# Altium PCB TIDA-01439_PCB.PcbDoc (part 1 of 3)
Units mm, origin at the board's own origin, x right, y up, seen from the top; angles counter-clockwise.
Board outline 105.8 x 40.5 mm, 4 copper layers (Layer 1 - Top Layer, Layer 2 - GND, Layer 3 - POWER, Layer 4 - Bottom Layer), stack 1.56 mm thick; 145 components, 123 nets, 523 pads, 227 vias.
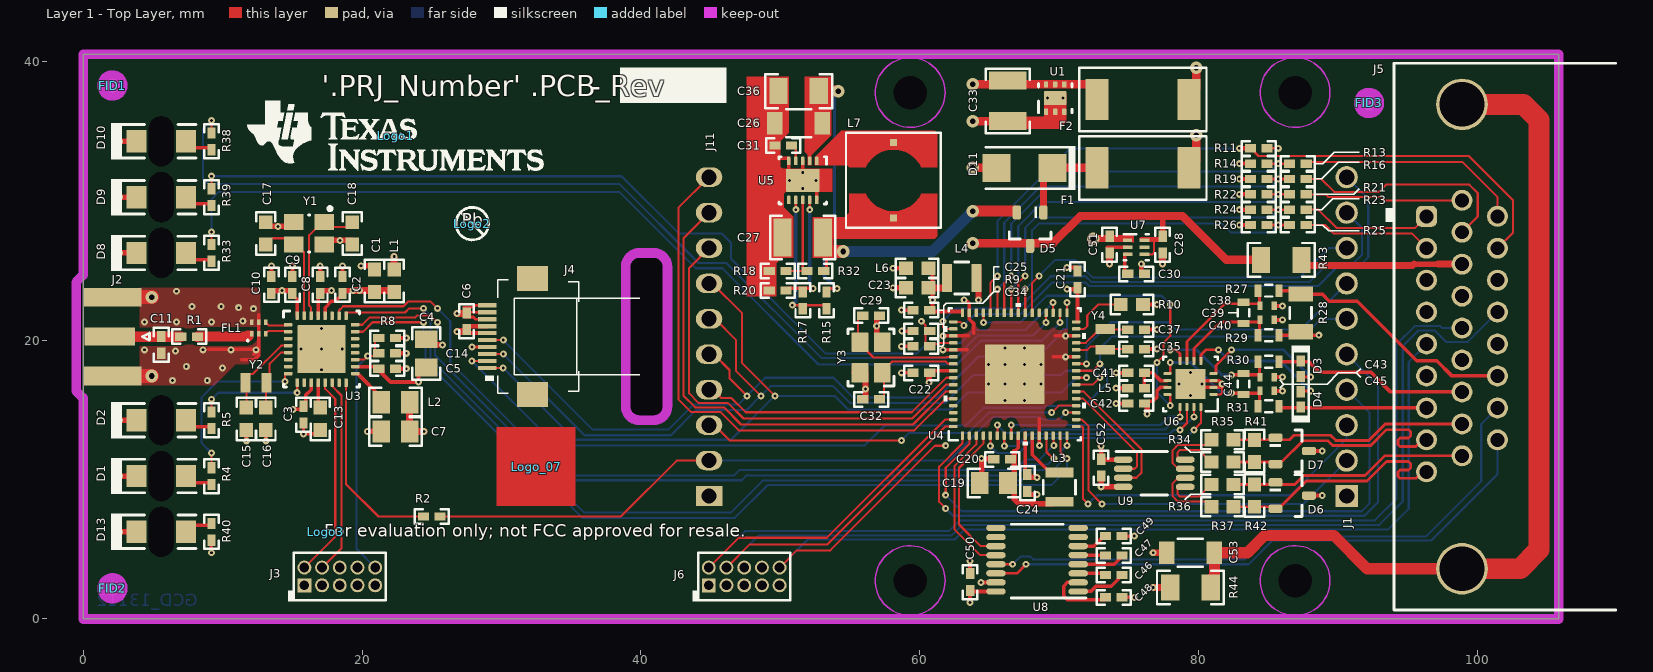
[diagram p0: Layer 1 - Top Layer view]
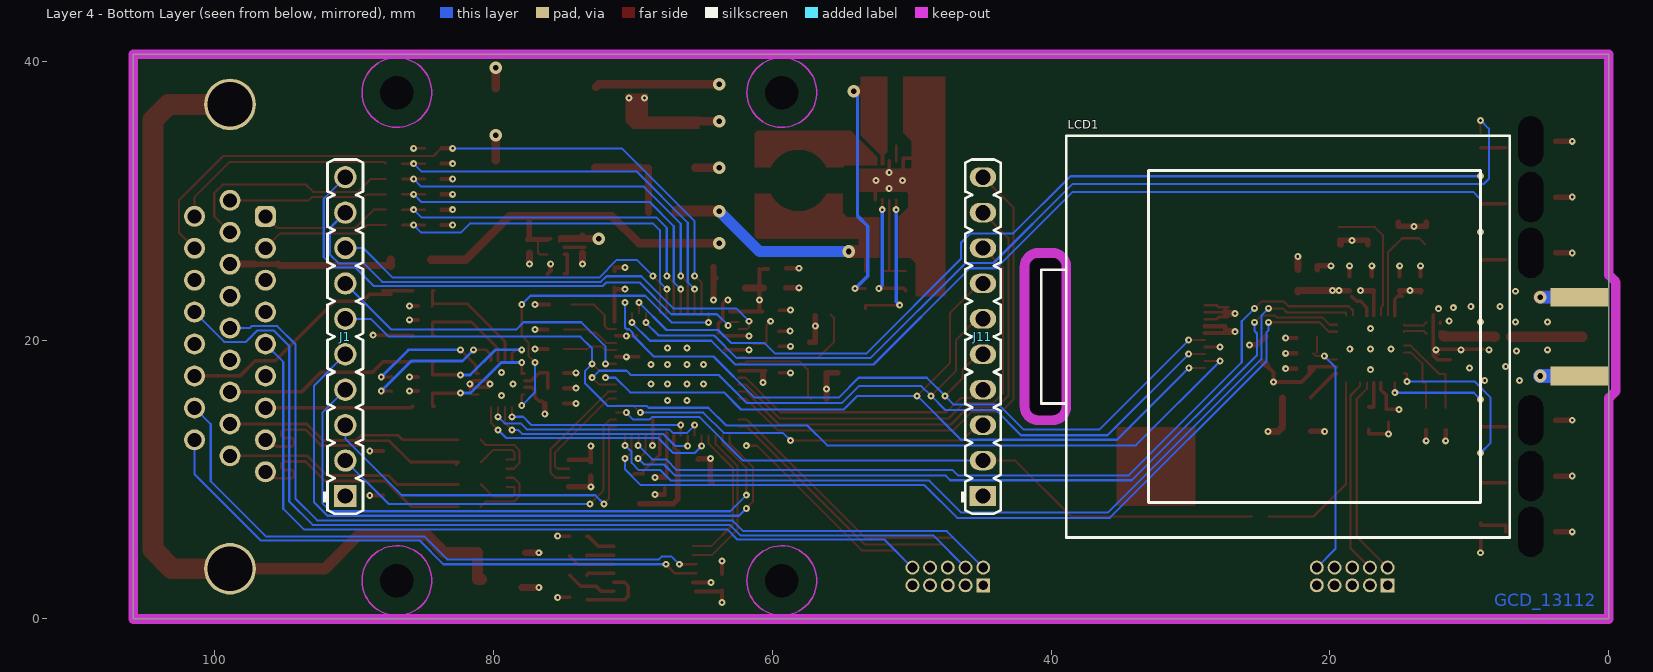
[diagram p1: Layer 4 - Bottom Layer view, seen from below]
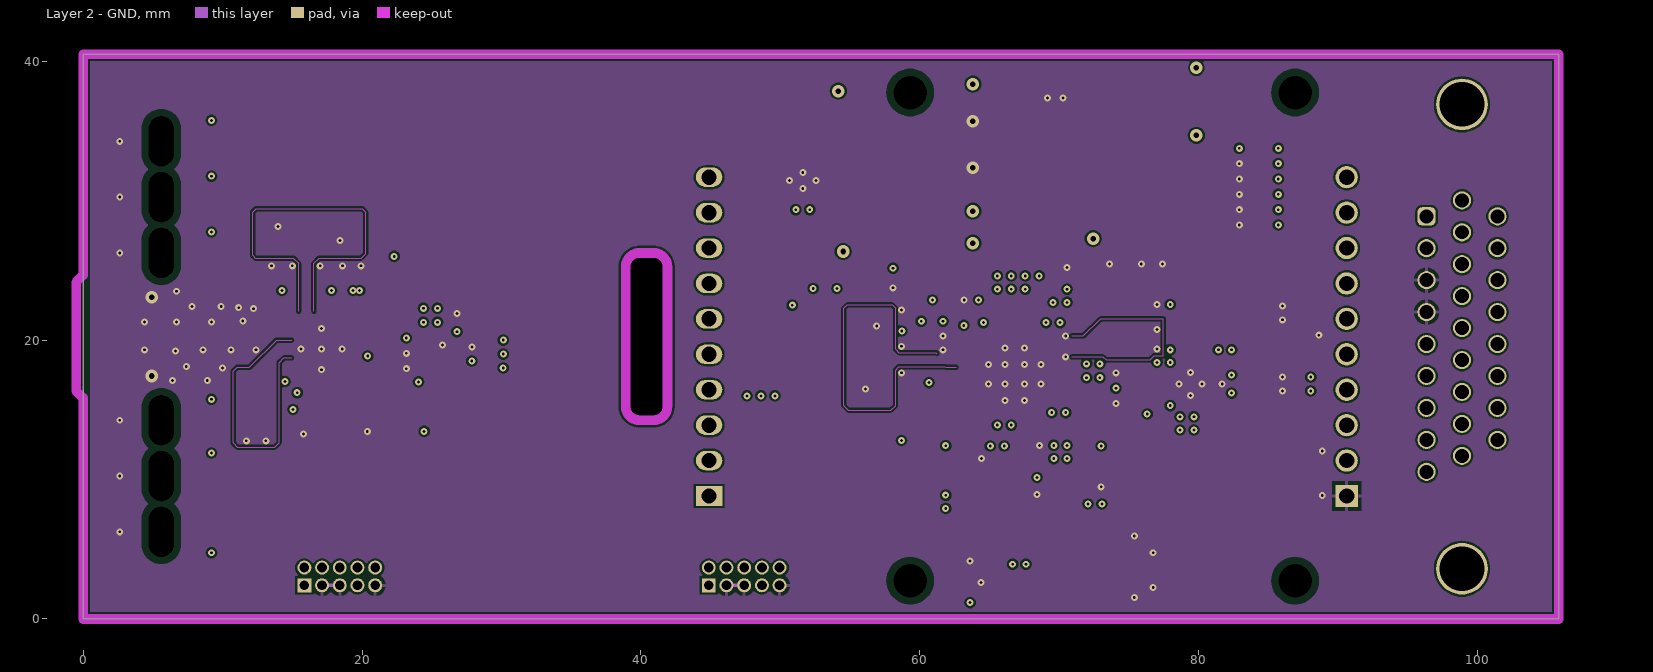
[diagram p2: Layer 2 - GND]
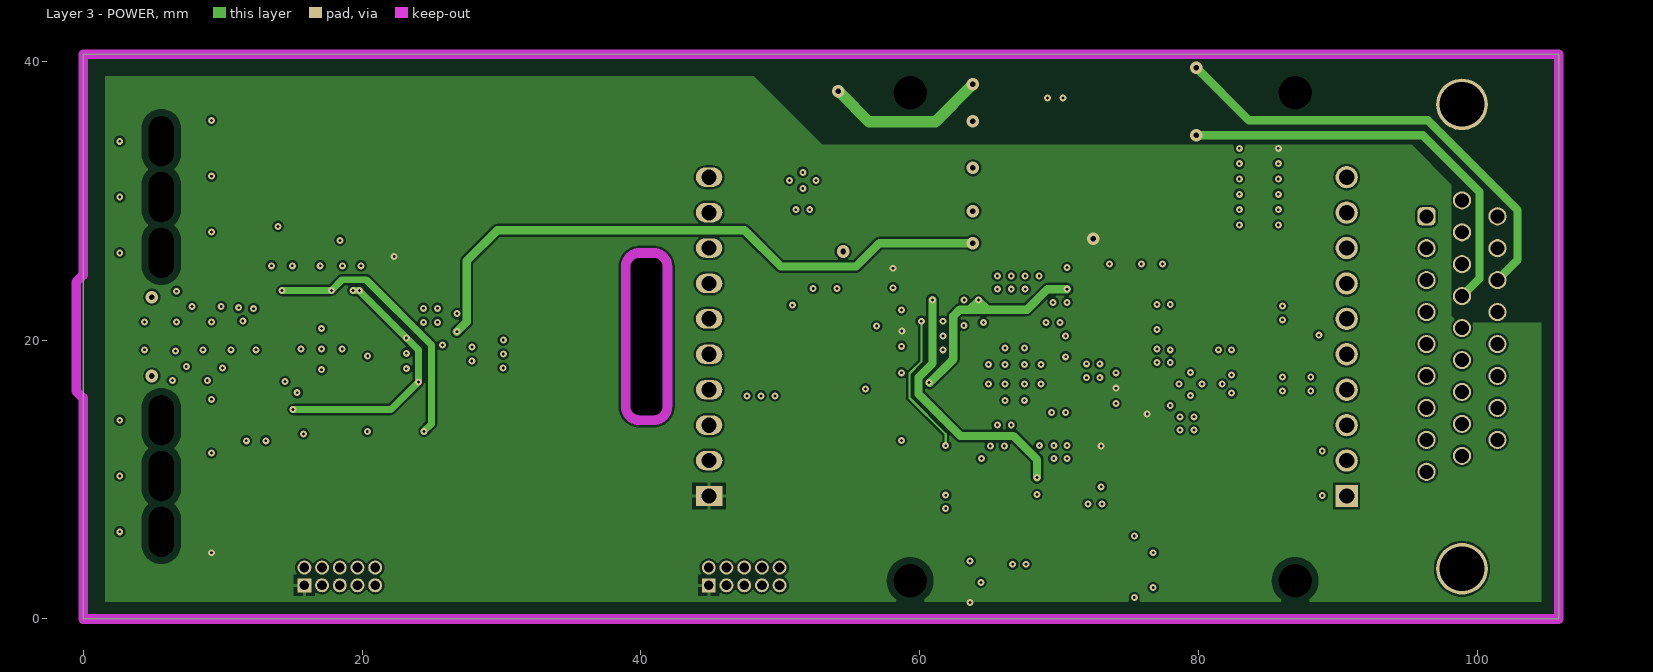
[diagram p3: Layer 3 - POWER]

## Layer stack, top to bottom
Top Solder: solder mask 0.0102, Solder Resist, Dk 3.5
Layer 1 - Top Layer: signal copper 0.0356
Dielectric1: prepreg 0.4724, 370HR, Dk 4.2
Layer 2 - GND: signal copper 0.0356
Dielectric3: core 0.4724, 370HR, Dk 4.2
Layer 3 - POWER: signal copper 0.0356
Dielectric2: prepreg 0.4724, 370HR, Dk 4.2
Layer 4 - Bottom Layer: signal copper 0.0356
Bottom Solder: solder mask 0.0102, Solder Resist, Dk 3.5

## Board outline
0,0 0,40.5 105.8,40.5 105.8,0
cut-out: 38.9,15.25 38.9,25.25 cw(c39.9,25.25) 39.9,26.25 40.9,26.25 cw(c40.9,25.25) 41.9,25.25 41.9,15.25 cw(c40.9,15.25) 40.9,14.25 39.9,14.25 cw(c39.9,15.25)

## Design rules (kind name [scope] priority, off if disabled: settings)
AssemblyTestPointUsage [All] p1: valid=2
BoardOutlineClearance [IsElectrical and not InComponent('J2')] p1: gap=0.5 ignorepadtopadclearanceinfootprint=FALSE
Clearance Clearance_PolyOnTop [(OnTop or OnBottom) and InPolygon] p1: gap=0.3 ignorepadtopadclearanceinfootprint=FALSE except(0: Arc-Hole Track-Hole SMDPad-Hole THPad-Hole Via-Hole Fill-Hole Poly-Hole Region-Hole Text-Hole)
Clearance Clearance_to-NPTHs [((ObjectKind = 'Pad') And (Layer = 'MultiLayer') And (PadIsPlated = 'False')) And (((AsMM(PadXSize_AllLayers) = 0.1) And (AsMM(PadYSize_AllLayers) = 0.1)) or (HoleType = 'Slot'))] p2: gap=0.5 ignorepadtopadclearanceinfootprint=FALSE except(0: Arc-Hole Track-Hole SMDPad-Hole THPad-Hole Via-Hole Fill-Hole Poly-Hole Region-Hole Text-Hole; 0.15: SMDPad-THPad)
Clearance Clearance_FiducialMark [IsKeepOut and InComponentClass('FiducialMark') vs IsPad and InComponentClass('FiducialMark')] p3: gap=0 ignorepadtopadclearanceinfootprint=FALSE
Clearance [All] p4: gap=0.15 ignorepadtopadclearanceinfootprint=FALSE except(0: Arc-Hole Track-Hole SMDPad-Hole THPad-Hole Via-Hole Fill-Hole Poly-Hole Region-Hole Text-Hole)
ComponentClearance ComponentClearance_Housing-to-J1 [(ObjectKind = '3D Body') And (Identifier = '82402224_BS_402_DIS-7024') vs InComponent('J1','J2','J5','J11')] p1: gap=0 collisioncheckmode=3 verticalgap=0 showdistances=FALSE
ComponentClearance [All  and not InComponent('FID3') vs All  and not InComponent('J5')] p2: gap=0.254 collisioncheckmode=3 verticalgap=0.254 showdistances=FALSE
DiffPairsRouting [All] p1: maxlimit=10 minlimit=0.125 mostfreqgap=0.15 toplayer_minwidth=0.381 toplayer_maxwidth=0.381 toplayer_prefwidth=0.381 midlayer1_minwidth=0.381 midlayer1_maxwidth=0.381 midlayer1_prefwidth=0.381 midlayer2_minwidth=0.381 midlayer2_maxwidth=0.381 midlayer2_prefwidth=0.381 bottomlayer_minwidth=0.381 bottomlayer_maxwidth=0.381 bottomlayer_prefwidth=0.381 maxuncoupledlength=12.7
FabricationTestPointUsage FabricationTestPointUsage_1 [All] p1: valid=2 allowmultiple=FALSE
FabricationTestpoint FabricationTestpoint_1 [All] p1: side=3 testpointundercomponent=TRUE minsize=1.016 maxsize=2.54 preferedsize=1.524 minholesize=0 maxholesize=1.016 preferedholesize=0.813 testpointgrid=0.025 allowsidetop=TRUE allowsidebottom=TRUE usegrid=TRUE gridtolerance=0
HoleSize [All] p1: absolutevalues=TRUE maxlimit=6 minlimit=0.2 maxpercent=80.000 minpercent=20.000
HoleSize FabricationTestpoint [All] p2 off: absolutevalues=TRUE maxlimit=2.54 minlimit=0.025 maxpercent=80.000 minpercent=20.000
HoleSize FabricationTestPointUsage [All] p3 off: absolutevalues=TRUE maxlimit=2.54 minlimit=0.025 maxpercent=80.000 minpercent=20.000
HoleToHoleClearance [All] p1: gap=0.2 allowstackedmicrovias=TRUE
MinimumAnnularRing [All] p1: minimumring=0.15
MinimumSolderMaskSliver [All] p1: minsoldermaskwidth=0.09
PlaneClearance [All] p1: clearance=0.5
PlaneConnect [All] p1: planeconnectstyle=Relief reliefexpansion=0.4 reliefentries=4 reliefconductorwidth=0.15 reliefairgap=0.15
PolygonConnect PolygonConnect_DirectConnect [(ObjectKind = 'Poly') And (Name = 'PolyDirectConnect')] p1: connectstyle=Direct reliefconductorwidth=0.254 reliefentries=4 polygonreliefangle="90 Angle" airgapwidth=0.254
PolygonConnect [IsVia] p2: connectstyle=Direct reliefconductorwidth=0.15 reliefentries=4 polygonreliefangle="90 Angle" airgapwidth=0.254
PolygonConnect "PolygonConnect_Thermal Relief" [All and not IsVia] p3: connectstyle=Relief reliefconductorwidth=0.25 reliefentries=4 polygonreliefangle="90 Angle" airgapwidth=0.25
PolygonConnect PolygonConnect_SMD [InPadClass('PolySMD')] p4: connectstyle=Relief reliefconductorwidth=0.254 reliefentries=4 polygonreliefangle="90 Angle" airgapwidth=0.254
RoutingCorners [All] p1: cornerstyle=45-Degree minsetback=1.25 maxsetback=1.25
RoutingVias [All] p1: holewidth=0.3 width=0.6 viastyle="Through Hole" minholewidth=0.2 minwidth=0.5 maxholewidth=0.6 maxwidth=1
SilkToBoardRegionClearance [Not ((IsComment or IsDesignator) And (Hide <> 'False')) and not InRegion(1000,500,4000,800)] p1:
SilkToSilkClearance [All and not InComponent('Logo2')] p1: silktosilkclearance=0.1
SilkToSolderMaskClearance [IsPad] p1: minsilkscreentomaskgap=0.1 clearancetoexposedcopper=TRUE
SolderMaskExpansion SolderMaskExpansion_Vias [IsVia] p1: expansion=0.025 soldermaskfromhole=TRUE
SolderMaskExpansion [All  and not IsVia] p2: expansion=0.05
Width [All] p1: maxlimit=10 minlimit=0.125 preferedwidth=0.15
16 further rules are at their usual default settings.

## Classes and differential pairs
component class TIDA-01439_CC2650: C1 C2 C3 C4 C5 C7 C8 C9 C10 C11 C13 C14 C15 C16 C17 C18 D1 D2 FL1 J2 J3 L1 L2 R1 R2 R4 R5 R8 U3 Y1 Y2
component class TIDA-01439_RTD: C38 C39 C40 C41 C42 C43 C44 C45 D3 D4 L5 R27 R28 R29 R30 R31 U6
component class TIDA-01439_Interface: C46 C47 C48 C49 C50 C52 C53 D6 D7 J5 R34 R35 R36 R37 R41 R42 R44 U8 U9
component class TIDA-01439_Powersupply: C26 C27 C28 C30 C31 C33 C36 C51 D5 D11 F1 F2 L7 R15 R17 R18 R20 R32 R43 U1 U5 U7
component class TIDA-01439_MSP432: C6 C19 C20 C21 C22 C23 C24 C25 C29 C32 C34 C35 C37 D8 D9 D10 D13 J1 J4 J6 J11 L3 L4 L6 R9 R10 R11 R13 R14 R16 R19 R21 R22 R23 R24 R25 R26 R33 R38 R39 R40 U4 Y3 Y4
component class Header: J1 J3 J6 J11
component class Logo: Logo1
component class TIDA-01439_EVM_Hardware: FID1 FID2 FID3 Logo1 Logo2 Logo3 ZZ1 ZZ2 ZZ3 ZZ4
component class FiducialMark: FID1 FID2 FID3
component class AssemblyNote: ZZ1 ZZ2 ZZ3 ZZ4

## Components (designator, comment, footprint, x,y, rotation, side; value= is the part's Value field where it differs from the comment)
C1 "Used in BOM report" 0603 20.9,24.25 r90 top
C2 "GRM155R70J104KA01D" 0402 18.6,23.95 r90 top value=0.1uF
C3 "GRM155R70J104KA01D" 0402 15.8,14.65 r270 top value=0.1uF
C4 "GRM21BR70J106KE76L" 0805_HV 24.6,19.05 r90 top value=10uF
C5 "GRM155R70J104KA01D" 0402 21.8,17.95 r0 top value=0.1uF
C6 "GRM155R70J104KA01D" 0402 27.5,21.35 r90 top value=0.1uF
C7 "GRM21BR70J106KE76L" 0805_HV 22.4,13.45 r180 top value=10uF
C8 "GRM155R70J104KA01D" 0402 17,23.95 r90 top value=0.1uF
C9 "GRM155R70J104KA01D" 0402 15,23.95 r90 top value=0.1uF
C10 "Used in BOM report" 0402 13.5,23.95 r90 top
C11 "Used in BOM report" 0402 5.6,19.65 r270 top
C13 "GRM188R70J105KA01D" 0603 17,14.35 r270 top value=1uF
C14 "GRM155R70J104KA01D" 0402 21.8,19.05 r0 top value=0.1uF
C15 "06035A220JAT2A" 0603 11.7,14.35 r90 top value=22pF
C16 "06035A220JAT2A" 0603 13.1,14.35 r270 top value=22pF
C17 "Used in BOM report" 0603 13.1,27.65 r90 top
C18 "Used in BOM report" 0603 19.3,27.65 r270 top
C19 "CC0805ZRY5V6BB475" 0805_HV 65.3,9.75 r180 top value=4.7uF
C20 "GRM155R70J104KA01D" 0402 65.9,11.45 r180 top value=0.1uF
C21 "GRM155R70J104KA01D" 0402 71.3,24.35 r90 top value=0.1uF
C22 "GRM155R70J104KA01D" 0402 60.1,17.65 r180 top value=0.1uF
C23 "GRM188R60J106ME47D" 0603 59.8,23.75 r180 top value=10uF
C24 "GRM155R70J104KA01D" 0402 67.7,9.75 r270 top value=0.1uF
C25 "GRM155R70J104KA01D" 0402 60.1,22.15 r180 top value=0.1uF
C26 "GRM31CR72A105KA01L" 1206_180 51.3,35.55 r180 top value=1uF
C27 "GRM32ER71A476KE15L" 1210_270 51.6,27.35 r180 top value=47uF
C28 "C1005X7S1A105K050BC" 0402 77.4,26.85 r270 top value=1uF
C29 "GRM1555C1H220JA01D" 0402 56.5,21.75 r180 top value=22pF
C30 "C1005X7R1C103K050BA" 0402 75.5,24.75 r0 top value=0.01uF
C31 "GRM155R71C473KA01D" 0402 50.2,33.95 r180 top value=0.047uF
C32 "GRM1555C1H220JA01D" 0402 56.5,15.75 r180 top value=22pF
C33 "GRM32ER71J106KA12L" 1210_270 66.3,37.15 r270 top value=10uF
C34 "GRM155R70J104KA01D" 0402 60.1,19.55 r180 top value=0.1uF
C35 "GRM1555C1H220JA01D" 0402 75.5,19.35 r180 top value=22pF
C36 "UMK316B7225KL-T" 1206 51.3,37.85 r180 top value=2.2uF
C37 "GRM1555C1H220JA01D" 0402 75.5,20.75 r180 top value=22pF
C38 "GRM155R72A182KA01D" 0402S 84.9,22.45 r0 top value=1800pF
C39 "C0603C183K1RACTU" 0603S 83.2,21.95 r270 top value=0.018uF
C40 "GRM155R72A182KA01D" 0402S 84.9,21.45 r180 top value=1800pF
C41 "GRM155R60J224KE01D" 0402 75.5,17.65 r180 top value=0.22uF
C42 "GRM155R60J224KE01D" 0402 75.5,15.45 r180 top value=0.22uF
C43 "GRM155R72A272KA01D" 0402S 84.9,17.35 r0 top value=2700pF
C44 "C0603C273K1RACTU" 0603S 83.2,16.85 r270 top value=0.027uF
C45 "GRM155R72A272KA01D" 0402S 84.9,16.35 r180 top value=2700pF
C46 "GRM155R70J104KA01D" 0402 73.9,3.15 r180 top value=0.1uF
C47 "GRM155R70J104KA01D" 0402 73.9,4.55 r180 top value=0.1uF
C48 "GRM155R70J104KA01D" 0402 73.9,1.55 r0 top value=0.1uF
C49 "GRM155R70J104KA01D" 0402 73.9,5.95 r0 top value=0.1uF
C50 "GRM155R70J104KA01D" 0402 63.6,2.65 r90 top value=0.1uF
C51 "C1005X7S1A105K050BC" 0402 73.6,26.85 r270 top value=1uF
C52 "GRM155R70J104KA01D" 0402 73,10.85 r270 top value=0.1uF
C53 "GRM31CR72E104KW03L" 1206_180 79.4,4.75 r0 top value=0.1uF
D1 "KPTL-3216CGCK-01" KPTL-3216-01_Green 5.6,10.25 r180 top value=Green
D2 "KPTL-3216SURCK-01" KPTL-3216-01_Red 5.6,14.25 r180 top value=Red
D3 "ZHCS350TA" SOD-523 87.3,17.95 r270 top value=40V
D4 "ZHCS350TA" SOD-523 87.3,15.75 r90 top value=40V
D5 "BAT54C-7-F" SOT-23 67.9,27.95 r270 top value=30V
D6 "CDSOT23-SM712" SOT-23 86.7,8.85 r0 top value=7V
D7 "CDSOT23-SM712" SOT-23 86.7,12.05 r0 top value=7V
D8 "KPTL-3216CGCK-01" KPTL-3216-01_Green 5.6,26.25 r180 top value=Green
D9 "KPTL-3216SURCK-01" KPTL-3216-01_Red 5.6,30.25 r180 top value=Red
D10 "KPTL-3216CGCK-01" KPTL-3216-01_Green 5.6,34.25 r180 top value=Green
D11 "SMAJ5.0A-TR" SMA 67.5,32.35 r180 top value=5V
D13 "KPTL-3216CGCK-01" KPTL-3216-01_Green 5.6,6.25 r180 top value=Green
F1 "0459.500" PicoSMF459 76,32.35 r0 top
F2 "0459.500" PicoSMF459 76,37.25 r0 top
FID1 "Fiducial" Fiducial10-20 2.1,38.25 r0 top
FID2 "Fiducial" Fiducial10-20 2.1,2.2 r0 top
FID3 "Fiducial" Fiducial10-20 92.2,37 r0 top
FL1 "LFB182G45BG5D920" Murata_LFB182G45BG5D920 12.579,20.865 r90 top value="2.45 GHz"
J1 "61301011121" Wurth_61301011121#1 90.6,20.25 r90 bottom locked
J2 "SMA-J-P-H-ST-EM1" Samtec_SMA-J-P-H-ST-EM1 0,20.25 r270 top locked
J3 "GRPB052VWVN-RC" CONN_GRPB052VWVN-RC 18.4,3.05 r0 top
J4 "FH12-10S-0.5SH[55]" Hirose_FH12-10S-0_5SH[55] 30.6,20.25 r90 top locked
J5 "618026330923" Wurth_618026330923 110.3,20.25 r0 top locked
J6 "GRPB052VWVN-RC" CONN_GRPB052VWVN-RC 47.4,3.05 r0 top
J11 "61301011121" Wurth_61301011121#2 44.88,20.25 r90 bottom locked
L1 "BLM18HE152SN1D" 0603 22.3,24.25 r90 top value="1500 ohm"
L2 "CKS2125100M-T" 0805_HV 22.4,15.55 r0 top value=10uH
L3 "MLP2520S4R7ST0S1" MLP2520S-S 70,9.45 r270 top value=4.7uH
L4 "MLP2520S4R7ST0S1" MLP2520S-S 63,24.45 r0 top value=4.7uH
L5 "BLM15HG102SN1D" 0402 75.5,16.55 r0 top value="1000 ohm"
L6 "BLM18HE152SN1D" 0603 59.8,25.15 r180 top value="1500 ohm"
L7 "744053101" WE-TPC-LH 58.1,31.45 r270 top value=100uH
LCD1 "" LCD_LS013B7DH06 21.1,20.25 r270 bottom locked
Logo1 "Texas Instruments" TI_Stacked_Overlay_Small 22.4,34.65 r0 top
Logo2 "Pb-Free Symbol" Pb-Free_Overlay_Small 27.9,28.35 r0 top
Logo3 "FCC disclaimer" FCC_disclaimer 17.4,6.25 r0 top
Logo_07 "" GCD-Logo_5.5x5.5_SolderMask 32.475,10.925 r0 top
R1 "CRCW04020000Z0ED" 0402 7.6,20.25 r0 top value=0
R2 "CRCW04020000Z0ED" 0402 25,7.35 r0 top value=0
R4 "CRCW0402470RJNED" 0402 9.2,10.25 r90 top value=470
R5 "CRCW0402470RJNED" 0402 9.2,14.25 r270 top value=470
R8 "CRCW040247K5FKED" 0402 21.8,20.15 r0 top value=47.5k
R9 "CRCW0402100KJNED" 0402 60.1,20.65 r180 top value=100k
R10 "RG1608P-913-B-T5" 0603 75.2,22.55 r180 top value=91.0k
R11 "CRCW040210K0FKED" 0402 84.3,33.75 r0 top value=10.0k
R13 "CRCW040218K0FKED" 0402 87.1,32.65 r0 top value=18.0k
R14 "CRCW040233K0JNED" 0402 84.3,32.65 r0 top value=33k
R15 "CRCW04022M00FKED" 0402 53.3,22.85 r90 top value=2.00Meg
R16 "CRCW040218K0FKED" 0402 87.1,31.55 r0 top value=18.0k
R17 "CRCW0402130KJNED" 0402 51.6,22.85 r270 top value=130k
R18 "CRCW0402110KFKED" 0402 49.8,24.95 r0 top value=110k
R19 "CRCW040233K0JNED" 0402 84.3,31.55 r0 top value=33k
R20 "CRCW040224K9FKED" 0402 49.8,23.55 r0 top value=24.9k
R21 "CRCW040218K0FKED" 0402 87.1,30.45 r0 top value=18.0k
R22 "CRCW040233K0JNED" 0402 84.3,30.45 r0 top value=33k
R23 "CRCW040218K0FKED" 0402 87.1,29.35 r0 top value=18.0k
R24 "CRCW040233K0JNED" 0402 84.3,29.35 r0 top value=33k
R25 "CRCW040218K0FKED" 0402 87.1,28.25 r0 top value=18.0k
R26 "CRCW040233K0JNED" 0402 84.3,28.25 r0 top value=33k
R27 "RG1608P-4121-B-T5" 0603S 85,23.55 r180 top value=4.12k
R28 "PFC-W1206R-12-3241-B" 1206L 87.3,21.95 r90 top value=3.24k
R29 "RG1608P-4121-B-T5" 0603S 85,20.35 r180 top value=4.12k
R30 "RG1608P-4121-B-T5" 0603S 85,18.45 r180 top value=4.12k
R31 "RG1608P-4121-B-T5" 0603S 85,15.25 r180 top value=4.12k
R32 "CRCW0402383KFKED" 0402 52.5,24.95 r0 top value=383k
R33 "CRCW0402470RJNED" 0402 9.2,26.25 r90 top value=470
R34 "CRCW060310R0JNEAHP" 0603 81.7,11.25 r0 top value=10
R35 "CRCW060310R0JNEAHP" 0603 81.7,12.85 r0 top value=10
R36 "CRCW060310R0JNEAHP" 0603 81.7,9.65 r0 top value=10
R37 "CRCW060310R0JNEAHP" 0603 81.7,8.05 r0 top value=10
R38 "CRCW0402470RJNED" 0402 9.2,34.25 r270 top value=470
R39 "CRCW0402470RJNED" 0402 9.2,30.25 r270 top value=470
R40 "CRCW0402470RJNED" 0402 9.2,6.25 r90 top value=470
R41 "CRCW0603120RJNEA" 0603 84,12.05 r90 top value=120
R42 "CRCW0603120RJNEA" 0603 84,8.85 r270 top value=120
R43 "CRCW1206100RJNEA" 1206 85.9,25.75 r0 top value=100
R44 "CRCW1206100RJNEA" 1206 79.4,2.25 r0 top value=100
U1 "TVS3300DRVR" DRV0006A 69.7,37.35 r90 top
U3 "CC2650F128RHBR" RHB0032E 17.1,19.35 r0 top
U4 "MSP432P401RIRGCR" RGC0064B 66.8,17.55 r90 top
U5 "LM5165DRCR" DRC0010J 51.6,31.45 r270 top
U6 "ADS1220IRVAR" RVA0016A 79.4,16.85 r180 top
U7 "TPS71733DSER" DSE0006A 75.5,26.65 r0 top
U8 "MAX3232EIPWR" PW0016A_N 68.4,4.25 r180 top
U9 "SN65HVD71DGKR" DGK0008A_N 76.8,10.45 r0 top
Y1 "TSX-3225 24.0000MF20G-AC3" EPSON_TSX-3225 16.2,27.65 r270 top
Y2 "FC-12M 32.7680KA-A3" Epson_FC-12M 12.4,16.95 r0 top
Y3 "FA-238 48.0000MB-W0" Epson_FA-238 56.5,18.75 r180 top
Y4 "FC-12M 32.7680KA-A3" Epson_FC-12M 73.3,20.05 r270 top
ZZ1 "This Assembly Note is for PCB labels only" AssemblyNoteLabel 4.399,82.075 r0 top
ZZ2 "These assemblies are ESD sensitive, ESD precautions shall be observed." AssemblyNote 4.399,79.309 r0 top
ZZ3 "These assemblies must be clean and free from flux and all contaminants. Use of no clean flux is not acceptable." AssemblyNote 4.399,77.06 r0 top
ZZ4 "These assemblies must comply with workmanship standards IPC-A-610 Class 2, unless otherwise specified." AssemblyNote 4.399,74.811 r0 top

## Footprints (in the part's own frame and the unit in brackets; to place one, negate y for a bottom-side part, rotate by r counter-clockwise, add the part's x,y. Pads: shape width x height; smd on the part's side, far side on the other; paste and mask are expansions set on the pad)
0402 [mm] "0402 from SM-752 data"
  rect 0.8x0.6 smd: 1(-0.6,0) 2(0.6,0)
  silkscreen extent -1.22,-0.52 1.22,0.52, body extent -0.55,-0.3 0.55,0.3, height 0.6
0402S [mil] "Based on C0402S footprint from PADS legacy"
  rect 15x24 smd: 1(-20,0) 2(20,0)
  body extent -22,-12 22,12, height 24
0603 [mm] "0603 from SM-752 data"
  rect 1x0.95 smd: 1(-0.8,0) 2(0.8,0)
  silkscreen extent -1.52,-0.69 1.52,0.69, body extent -0.87,-0.47 0.87,0.47, height 1
0603S [mil]
  rect 20x35 smd: 1(-30,0) 2(30,0)
  silkscreen extent -10,-17 10,17, body extent -34,-19 34,19, height 39
0805_HV [mil] "0805 with 30mil clearance between pads"
  rect 50x63 smd: 1(-40,0) 2(40,0)
  silkscreen extent -74,-40 74,40, body extent -43,-29 43,29, height 57
1206 [mm] "1206 from SM-752 data"
  rect 1.3x1.85 smd: 1(-1.45,0) 2(1.45,0)
  silkscreen extent -2.4,-1.21 2.4,1.21, body extent -1.7,-0.9 1.7,0.9, height 1.35
1206_180 [mm] "1206_180"
  rect 1.1x1.6 smd: 1(-1.7,0) 2(1.7,0)
  silkscreen extent -0.9,-1 0.9,1, body extent -1.75,-0.95 1.75,0.95, height 1.8
1206L [mm] "1206 from SM-752 data"
  rect 1.1x1.75 smd: 1(-1.35,0) 2(1.35,0)
  silkscreen extent -0.4,-0.77 0.4,0.77, body extent -1.7,-0.9 1.7,0.9, height 1.35
1210_270 [mm] "1210"
  rect 1.3x2.7 smd: 1(-1.45,0) 2(1.45,0)
  silkscreen extent -2.32,-1.57 2.32,1.57, body extent -1.7,-1.35 1.7,1.35, height 2.7
AssemblyNote [mm] "Assembly Note"
AssemblyNoteLabel [mm] "Assembly Note for PCB Labels"
CONN_GRPB052VWVN-RC [mm] "SULLINS"
  rect 1x1 hole 0.7 mask+0.08: 1(-2.54,-0.635)
  round 1 hole 0.7 mask+0.08: 2(-2.54,0.635) 3(-1.27,-0.635) 4(-1.27,0.635) 5(0,-0.635) 6(0,0.635) 7(1.27,-0.635) 8(1.27,0.635) 9(2.54,-0.635) 10(2.54,0.635)
  silkscreen extent -3.7,-1.8 3.3,1.7, body extent -3.17,-1.7 3.17,1.7, height 4
DGK0008A_N [mm] "TSOP, 8-Leads, Body 3x3mm, Pitch 0.65mm, IPC Medium Density"
  oval 1.35x0.45 smd: 1(-2.225,0.975) 2(-2.225,0.325) 3(-2.225,-0.325) 4(-2.225,-0.975) 5(2.225,-0.975) 6(2.225,-0.325) 7(2.225,0.325) 8(2.225,0.975)
  silkscreen extent -2.75,-1.55 0.95,1.55, body extent -2.45,-1.5 2.45,1.5, height 0.96
DRC0010J [mm] "SON, 10-Leads, Body 3x3mm, Pitch 0.5mm, Thermal Pad 2.4x1.65mm, TI Recommended"
  rrect42% 0.6x0.24 smd: 1(-1.4,1) 2(-1.4,0.5) 3(-1.4,0) 4(-1.4,-0.5) 5(-1.4,-1) 6(1.4,-1) 7(1.4,-0.5) 8(1.4,0) 9(1.4,0.5) 10(1.4,1)
  rrect6% 1.65x2.4 smd paste-0.825: 11(0,0)
  silkscreen extent -1.7,-1.7 1.7,1.7, body extent -1.5,-1.5 1.5,1.5, height 0.77
DRV0006A [mm] "SON, 6-Leads, Body 2x2mm, Pitch 0.65mm, Thermal Pad 1.6x1mm, TI Recommended"
  rrect33% 0.45x0.3 smd: 1(-0.975,0.65) 2(-0.975,0) 3(-0.975,-0.65) 4(0.975,-0.65) 5(0.975,0) 6(0.975,0.65)
  rrect14% 1x0.7 on Top Paste: 7(0,0.45) 7(0,-0.45)
  rrect10% 1x1.6 smd paste-0.5: 7(0,0)
  silkscreen extent -1.05,-1.2 1.05,1.2, body extent -1.05,-1.05 1.05,1.05, height 0.81
DSE0006A [mm] "TI recommended land pattern"
  rect 0.66x0.25 smd: 1(-0.62,0.5)
  rect 0.7x0.25 smd: 2(-0.6,0) 3(-0.6,-0.5) 4(0.6,-0.5) 5(0.6,0) 6(0.6,0.5)
  Layer 1 - Top Layer region: -0.3,0.625 -0.25,0.625 -0.15,0.525 -0.15,0.375 -0.3,0.375
  silkscreen extent -0.9,-0.92 0.9,0.92, body extent -0.77,-0.77 0.77,0.77, height 0.8
Epson_FA-238 [mm] "SMD, 4-Leads, Body 3.2x2.5mm"
  rrect8% 1.2x1.4 smd: 1(-0.8,1.1) 2(-0.8,-1.1) 3(0.8,-1.1) 4(0.8,1.1)
  silkscreen extent -1.65,-2.05 1.65,2.05, body extent -1.3,-1.65 1.3,1.65, height 0.7
Epson_FC-12M [mm] "Epson"
  rect 0.7x1.4 smd: 1(-0.75,0) 2(0.75,0)
  body extent -1.05,-0.63 1.05,0.63, height 0.6
EPSON_TSX-3225 [mm] "SMD, 4-Leads, Body 2.65x3.35mm, Height 0.6mm"
  rect 1.15x1.4 smd: 1(-0.8,1.1) 2(-0.8,-1.1) 3(0.8,-1.1) 4(0.8,1.1)
  silkscreen extent -1.9,-0.05 1.33,1.63, body extent -1.33,-1.68 1.33,1.68, height 0.61
FCC_disclaimer [mm]
Fiducial10-20 [mm]
  round 1 smd mask+0.5: 1(0,0)
  Layer 1 - Top Layer keep-out circle w1.178: c0,0 r0.5
GCD-Logo_5.5x5.5_SolderMask [mm] "GCD-Logo, 5.55x5.55mm, SolderMask, 80µm, positive"
Hirose_FH12-10S-0_5SH[55] [mm] "Hirose, footprint recommended"
  rect 0.3x1.3 smd: 1(-2.254,1.626) 2(-1.754,1.626) 3(-1.254,1.626) 4(-0.754,1.626) 5(-0.253,1.626) 6(0.246,1.626) 7(0.746,1.626) 8(1.246,1.626) 9(1.746,1.626) 10(2.247,1.626)
  rect 1.8x2.2 smd: M1(-4.153,-1.622) M2(4.153,-1.626)
  silkscreen extent -4.06,-4.95 4.07,1.78, body extent -4.55,-4.88 4.56,0.84, height 2
KPTL-3216-01_Green [mm] "SMD, 2-Leads, Body 3.2x1.6mm"
  round 0 hole 1.8 slot 3.6 at 90 deg unplated: 0(0,0)
  rect 1.45x1.6 smd: 1(-1.78,0) 2(1.78,0)
  silkscreen extent -2.5,-1.3 3.6,1.3, body extent -1.65,-0.85 1.65,0.85, height 0.27
KPTL-3216-01_Red [mm] "SMD, 2-Leads, Body 3.2x1.6mm"
  round 0 hole 1.8 slot 3.6 at 90 deg unplated: 0(0,0)
  rect 1.45x1.6 smd: 1(-1.78,0) 2(1.78,0)
  silkscreen extent -2.5,-1.3 3.6,1.3, body extent -1.65,-0.85 1.65,0.85, height 0.27
LCD_LS013B7DH06 [mm] "Outline Display"
  silkscreen extent -14.4,-19.6 14.4,14, body extent -14.4,-17.8 14.4,14, height 0.85
MLP2520S-S [mm] "TDK"
  rect 0.7x2 smd: 1(-1.05,0) 2(1.05,0)
  silkscreen extent -0.5,-1.15 0.5,1.15, body extent -1.32,-1.07 1.32,1.07, height 1.2
Murata_LFB182G45BG5D920 [mm] "SMT, 6-Leads, Body 1.6x0.8mm, Pitch 0.5mm"
  rect 0.425x0.25 smd mask+0.07: 1(-0.413,0.5) 2(-0.413,0) 3(-0.413,-0.5) 4(0.412,-0.5) 5(0.412,0) 6(0.412,0.5)
  silkscreen extent -0.91,0.76 -0.89,0.78, body extent -0.45,-0.85 0.45,0.85, height 0.65
Pb-Free_Overlay_Small [mm]
  silkscreen extent -1.16,-1.17 1.17,1.17
PicoSMF459 [mm] "Littelfuse 459 Fuses, recommended land pattern"
  rect 1.65x2.97 smd: 1(-3.3,0) 2(3.3,0)
  silkscreen extent -4.57,-2.27 4.55,2.27, body extent -3.62,-2.17 3.61,2.14, height 3.05
PW0016A_N [mm] "TSOP, 16-Leads, Body 5x4.4mm, Pitch 0.65mm, IPC Medium Density"
  oval 1.4x0.45 smd: 1(-2.95,2.275) 2(-2.95,1.625) 3(-2.95,0.975) 4(-2.95,0.325) 5(-2.95,-0.325) 6(-2.95,-0.975) 7(-2.95,-1.625) 8(-2.95,-2.275) 9(2.95,-2.275) 10(2.95,-1.625) 11(2.95,-0.975) 12(2.95,-0.325) 13(2.95,0.325) 14(2.95,0.975) 15(2.95,1.625) 16(2.95,2.275)
  silkscreen extent -3.5,-2.55 1.85,2.75, body extent -3.21,-2.5 3.21,2.5, height 1
RGC0064B [mm]
  rrect42% 0.6x0.24 smd mask+0.07: 1(-4.4,3.75) 2(-4.4,3.25) 3(-4.4,2.75) 4(-4.4,2.25) 5(-4.4,1.75) 6(-4.4,1.25) 7(-4.4,0.75) 8(-4.4,0.25) 9(-4.4,-0.25) 10(-4.4,-0.75) 11(-4.4,-1.25) 12(-4.4,-1.75) 13(-4.4,-2.25) 14(-4.4,-2.75) 15(-4.4,-3.25) 16(-4.4,-3.75) 33(4.4,-3.75) 34(4.4,-3.25) 35(4.4,-2.75) 36(4.4,-2.25) 37(4.4,-1.75) 38(4.4,-1.25) 39(4.4,-0.75) 40(4.4,-0.25) 41(4.4,0.25) 42(4.4,0.75) 43(4.4,1.25) 44(4.4,1.75) 45(4.4,2.25) 46(4.4,2.75) 47(4.4,3.25) 48(4.4,3.75)
  rrect42% 0.24x0.6 smd mask+0.07: 17(-3.751,-4.4) 18(-3.251,-4.4) 19(-2.751,-4.4) 20(-2.251,-4.4) 21(-1.75,-4.4) 22(-1.25,-4.4) 23(-0.75,-4.4) 24(-0.25,-4.4) 25(0.25,-4.4) 26(0.75,-4.4) 27(1.25,-4.4) 28(1.75,-4.4) 29(2.251,-4.4) 30(2.751,-4.4) 31(3.251,-4.4) 32(3.751,-4.4) 49(3.751,4.4) 50(3.251,4.4) 51(2.751,4.4) 52(2.251,4.4) 53(1.75,4.4) 54(1.25,4.4) 55(0.75,4.4) 56(0.25,4.4) 57(-0.25,4.4) 58(-0.75,4.4) 59(-1.25,4.4) 60(-1.75,4.4) 61(-2.251,4.4) 62(-2.751,4.4) 63(-3.251,4.4) 64(-3.751,4.4)
  rrect8% 1.19x1.19 on Top Paste: 65(-1.39,-1.39) 65(-1.39,0) 65(-1.39,1.39) 65(0,1.39) 65(0,0) 65(0,-1.39) 65(1.39,-1.39) 65(1.39,0) 65(1.39,1.39)
  rrect2% 4.25x4.25 smd paste-2.112: 65(0,0)
  silkscreen extent -5.1,-5.1 5.1,5.1, body extent -4.57,-4.57 4.57,4.57, height 1.01
RHB0032E [mm] "QFN, 32-Leads, Body 5x5mm, Pitch 0.5mm, Thermal Pad 3.45x3.45mm, TI Recommended"
  rrect40% 0.6x0.25 smd: 1(-2.4,1.75) 2(-2.4,1.25) 3(-2.4,0.75) 4(-2.4,0.25) 5(-2.4,-0.25) 6(-2.4,-0.75) 7(-2.4,-1.25) 8(-2.4,-1.75) 17(2.4,-1.75) 18(2.4,-1.25) 19(2.4,-0.75) 20(2.4,-0.25) 21(2.4,0.25) 22(2.4,0.75) 23(2.4,1.25) 24(2.4,1.75)
  rrect40% 0.25x0.6 smd: 9(-1.75,-2.4) 10(-1.25,-2.4) 11(-0.75,-2.4) 12(-0.25,-2.4) 13(0.25,-2.4) 14(0.75,-2.4) 15(1.25,-2.4) 16(1.75,-2.4) 25(1.75,2.4) 26(1.25,2.4) 27(0.75,2.4) 28(0.25,2.4) 29(-0.25,2.4) 30(-0.75,2.4) 31(-1.25,2.4) 32(-1.75,2.4)
  rrect3% 3.45x3.45 smd paste-1.725: 33(0,0)
  rrect7% 1.49x1.49 on Top Paste: ""(-0.845,-0.845) ""(-0.845,0.845) ""(0.845,-0.845) ""(0.845,0.845)
  silkscreen extent -2.72,-2.73 2.72,2.73, body extent -2.57,-2.57 2.58,2.58, height 1.01
RVA0016A [mm] "QFN, 16-Leads, Body 3.5x3.5mm, Pitch 0.5mm, Thermal Pad 2.14x2.14mm, TI Recommended"
  oval 0.6x0.24 smd: 1(-1.65,0.75) 2(-1.65,0.25) 3(-1.65,-0.25) 4(-1.65,-0.75) 9(1.65,-0.75) 10(1.65,-0.25) 11(1.65,0.25) 12(1.65,0.75)
  oval 0.24x0.6 smd: 5(-0.75,-1.65) 6(-0.25,-1.65) 7(0.25,-1.65) 8(0.75,-1.65) 13(0.75,1.65) 14(0.25,1.65) 15(-0.25,1.65) 16(-0.75,1.65)
  rect 2.14x2.14 smd paste-1.07: 17(0,0)
  silkscreen extent -1.95,-1.95 1.95,1.95, body extent -1.8,-1.8 1.8,1.8, height 1.01
Samtec_SMA-J-P-H-ST-EM1 [mm] "SMA Jack, R/A, SMT"
  rect 1.27x3.6 smd: 1(0,1.9)
  rect 1.35x4.2 smd: 2(-2.825,2.1) 3(2.825,2.1)
  rect 1.35x4.2 smd far side: 4(-2.825,2.1) 5(2.825,2.1)
  silkscreen extent -0.25,4.25 0.25,4.75, body extent -3.17,-9.52 3.18,3.81, height 3.8
SMA [mm] "Molded Diode, 2-Leads, Body 4.3x2.6mm, IPC Medium Density, based on OnSemi component dimensions and land pattern"
  rect 2x2 smd: 1(-2,0) 2(2,0)
  silkscreen extent -3.66,-1.57 2.79,1.57, body extent -2.6,-1.3 2.6,1.3, height 2.42
SOD-523 [mm] "NXP Semiconductor recommended land pattern, nominal STEP model"
  rect 0.8x0.6 smd paste-0.05: 1(-0.55,0) 2(0.55,0)
  silkscreen extent -1.65,-0.66 1.2,0.66, body extent -0.8,-0.4 0.8,0.4, height 0.72
SOT-23 [mm] "SOT23, 3-Leads, Body 2.9x1.3mm, Pitch 0.95mm, Lead Span 2.5mm, IPC Medium Density"
  rrect50% 1x0.6 smd: 1(-1.2,0.95) 2(-1.2,-0.95) 3(1.2,0)
  silkscreen extent -1.63,-1.5 0.7,1.5, body extent -1.16,-1.45 1.21,1.45, height 1
TI_Stacked_Overlay_Small [mm]
  silkscreen extent -10.63,-2.49 10.63,2.49
WE-TPC-LH [mm] "Wurth Elektronik recommended land pattern, 2009-01-15"
  rect 0.5x0.5 smd: 1(-2.7,0) 2(2.7,0)
  Layer 1 - Top Layer region: 0.95,3.15 0.95,3.15 0.95,1.987 1.228,1.838 1.563,1.563 1.838,1.228 2.042,0.846 2.168,0.431 2.211,0 2.168,-0.431 2.042,-0.846 1.838,-1.228 1.563,-1.563 1.228,-1.838 0.95,-1.987 0.95,-3.15 3.15,-3.15 3.15,-3.15 3.15,3.15 0.95,3.15
  Layer 1 - Top Layer region: -0.95,3.15 -0.95,3.15 -0.95,1.987 -1.228,1.838 -1.563,1.563 -1.838,1.228 -2.042,0.846 -2.168,0.431 -2.211,0 -2.168,-0.431 -2.042,-0.846 -1.838,-1.228 -1.563,-1.563 -1.228,-1.838 -0.95,-1.987 -0.95,-3.15 -3.15,-3.15 -3.15,-3.15 -3.15,3.15 -0.95,3.15
  silkscreen extent -3.4,-3.4 3.4,3.4, body extent -3.05,-3.05 3.05,3.05, height 3
Wurth_61301011121#1 [mm] "Header, 2.54mm, 10x1, TH"
  rect 1.6x1.6 hole 1.1: 1(-11.43,0)
  round 1.6 hole 1.1: 2(-8.89,0) 3(-6.35,0) 4(-3.81,0) 5(-1.27,0) 6(1.27,0) 7(3.81,0) 8(6.35,0) 9(8.89,0) 10(11.43,0)
  silkscreen extent -12.7,-1.27 12.7,1.59, body extent -12.7,-1.27 12.7,1.27, height 8.54
Wurth_61301011121#2 [mm] "Header, 2.54mm, 10x1, TH"
  rect 1.4x1.9 hole 1.1: 1(-11.43,0)
  oval 1.4x1.9 hole 1.1: 2(-8.89,0) 3(-6.35,0) 4(-3.81,0) 5(-1.27,0) 6(1.27,0) 7(3.81,0) 8(6.35,0) 9(8.89,0) 10(11.43,0)
  silkscreen extent -12.7,-1.27 12.7,1.59, body extent -12.7,-1.27 12.7,1.27, height 8.54
Wurth_618026330923 [mm] "Receptacle, D-Sub, 2.29mm, 26 Pos, R/A, TH"
  rrect50% 1.5x1.5 / inner rrect50% 1.3x1.3 / far side rrect50% 1.5x1.5 hole 1: 1(-13.97,8.625)
  round 1.5 / inner round 1.3 / far side round 1.5 hole 1: 2(-13.97,6.335) 3(-13.97,4.045) 4(-13.97,1.755) 5(-13.97,-0.535) 6(-13.97,-2.825) 7(-13.97,-5.115) 8(-13.97,-7.405) 9(-13.97,-9.695) 10(-11.43,9.77) 11(-11.43,7.48) 12(-11.43,5.19) 13(-11.43,2.9) 14(-11.43,0.61) 15(-11.43,-1.68) 16(-11.43,-3.97) 17(-11.43,-6.26) 18(-11.43,-8.55) 19(-8.89,8.625) 20(-8.89,6.335) 21(-8.89,4.045) 22(-8.89,1.755) 23(-8.89,-0.535) 24(-8.89,-2.825) 25(-8.89,-5.115) 26(-8.89,-7.405)
  round 3.7 hole 3.2: S1(-11.43,16.65) S2(-11.43,-16.65)
  silkscreen extent -16.9,-19.6 -0.4,19.6, body extent -16.3,-19.6 6,19.6, height 12.52

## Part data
C1 C10 C11 C17 C18: library part Capacitor, "CAP, CERM, xxxF, xxV, [TempCo], xx%, [PackageReference]", Alternate Manufacturer=-
C2 C3 C5 C6 C8 C9 C14 C20 C21 C22 C24 C25 C34 C46 C47 C48 C49 C50 C52: "CAP, CERM, 0.1 µF, 6.3 V, +/- 10%, X7R, 0402", Cap_Case=0402, Manufacturer=MuRata, Supplier Part Number 1=GRM155R70J104KA01D-ND, TempCo=X7R, Tolerance_%=10, Value1=Unknown, Value2=6.3V, ValueDisplayed=0.1µF
C4 C7: "CAP, CERM, 10 µF, 6.3 V, +/- 10%, X7R, 0805", Cap_Case=0805, Manufacturer=MuRata, Supplier Part Number 1=490-3904-1-ND, TempCo=X7R, Tolerance_%=10, Value1=Unknown, Value2=6.3V, ValueDisplayed=10µF
C13: "CAP, CERM, 1 µF, 6.3 V, +/- 10%, X7R, 0603", Cap_Case=0603, Manufacturer=MuRata, Supplier Part Number 1=490-3898-1-ND, TempCo=X7R, Tolerance_%=10, Value1=Unknown, Value2=6.3V, ValueDisplayed=1µF
C15 C16: "CAP, CERM, 22 pF, 50 V,+/- 5%, C0G/NP0, 0603", Cap_Case=0603, Manufacturer=AVX, Supplier Part Number 1=478-1167-1-ND, TempCo=C0G/NP0, Tolerance_%=5, Value1="0.259 ohm", Value2=50V, ValueDisplayed=22pF
C19: "CAP, CERM, 4.7 µF, 10 V, +80/-20%, Y5V, 0805", Cap_Case=0805, Manufacturer="Yageo America", Supplier Part Number 1=311-1371-2-ND, TempCo=Y5V, Tolerance_%=80, Value1=Unknown, Value2=10V, ValueDisplayed=4.7µF
C23: "CAP, CERM, 10 µF, 6.3 V, +/- 20%, X5R, 0603", Cap_Case=0603, Manufacturer=MuRata, Supplier Part Number 1=490-3896-1-ND, TempCo=X5R, Tolerance_%=20, Value1="0.009 ohm", Value2=6.3V, ValueDisplayed=10µF
C26: "CAP, CERM, 1 µF, 100 V, +/- 10%, X7R, 1206", Cap_Case=2220, Manufacturer=MuRata, Supplier Part Number 1=490-3909-1-ND, TempCo=X7R, Tolerance_%=10, Value1=Unknown, Value2=100V, ValueDisplayed=1µF
C27: "CAP, CERM, 47 µF, 10 V, +/- 10%, X7R, 1210", Cap_Case=1210, Manufacturer=MuRata, Supplier Part Number 1=490-5312-1-ND, TempCo=X7R, Tolerance_%=10, Value1=Unknown, Value2=10V, ValueDisplayed=47µF
C28 C51: "CAP, CERM, 1 µF, 10 V, +/- 10%, X7S, 0402", Cap_Case=0402, Manufacturer=TDK, Supplier Part Number 1=445-9116-1-ND, TempCo=X7S, Tolerance_%=10, Value1=Unknown, Value2=10V, ValueDisplayed=1µF
C29 C32 C35 C37: "CAP, CERM, 22 pF, 50 V, +/- 5%, C0G/NP0, 0402", Cap_Case=0402, Manufacturer=MuRata, Supplier Part Number 1=81-GRM1555C1H220JA1D, TempCo=C0G/NP0, Tolerance_%=5, Value1=Unknown, Value2=50V, ValueDisplayed=22pF
C30: "CAP, CERM, 0.01 µF, 16 V, +/- 10%, X7R, 0402", Cap_Case=0402, Manufacturer=TDK, Supplier Part Number 1=445-1262-1-ND, TempCo=X7R, Tolerance_%=10, Value1="0.0623 ohm", Value2=16V, ValueDisplayed=0.01µF
C31: "CAP, CERM, 0.047 µF, 16 V, +/- 10%, X7R, 0402", Cap_Case=0402, Manufacturer=MuRata, Supplier Part Number 1=GRM155R71C473KA01D-ND, TempCo=X7R, Tolerance_%=10, Value1=Unknown, Value2=16V, ValueDisplayed=0.047µF
C33: "CAP, CERM, 10 µF, 63 V, +/- 10%, X7R, 1210", Cap_Case=1210, Manufacturer=MuRata, Supplier Part Number 1=490-9970-1-ND, TempCo=X7R, Tolerance_%=10, Value1=Unknown, Value2=63V, ValueDisplayed=10µF
C36: "CAP, CERM, 2.2 µF, 50 V, +/- 10%, X7R, 1206", Cap_Case=1206, Manufacturer="Taiyo Yuden", Supplier Part Number 1=587-2911-1-ND, TempCo=X7R, Tolerance_%=10, Value1=Unknown, Value2=50V, ValueDisplayed=2.2µF
C38 C40: "CAP, CERM, 1800pF, 100V, +/-10%, X7R, 0402", Cap_Case=0402, Manufacturer=MuRata, Supplier Part Number 1=GRM155R72A182KA01D-ND, TempCo=X7R, Tolerance_%=10, Value1=Unknown, Value2=100V, ValueDisplayed=1800pF
C39: "CAP, CERM, 0.018uF, 100V, +/-10%, X7R, 0603", Cap_Case=0603, Manufacturer=Kemet, Supplier Part Number 1=399-3475-1-ND, TempCo=X7R, Tolerance_%=10, Value1=Unknown, Value2=100V, ValueDisplayed=0.018µF
C41 C42: "CAP, CERM, 0.22uF, 6.3V, +/-10%, X5R, 0402", Cap_Case=0402, Manufacturer=MuRata, Supplier Part Number 1=490-5407-1-ND, TempCo=X5R, Tolerance_%=10, Value1=Unknown, Value2=6.3V, ValueDisplayed=0.22µF
C43 C45: "CAP, CERM, 2700pF, 100V, +/-10%, X7R, 0402", Cap_Case=0402, Manufacturer=MuRata, Supplier Part Number 1=GRM155R72A272KA01D-ND, TempCo=X7R, Tolerance_%=10, Value1=Unknown, Value2=100V, ValueDisplayed=2700pF
C44: "CAP, CERM, 0.027uF, 100V, +/-10%, X7R, 0603", Cap_Case=0603, Manufacturer=Kemet, Supplier Part Number 1=399-3477-1-ND, TempCo=X7R, Tolerance_%=10, Value1=Unknown, Value2=100V, ValueDisplayed=0.027µF
C53: "CAP, CERM, 0.1 µF, 250 V, +/- 10%, X7R, 1206", Cap_Case=1206, Manufacturer=MuRata, Supplier Part Number 1=490-3542-1-ND, TempCo=X7R, Tolerance_%=10, Value1=Unknown, Value2=250V, ValueDisplayed=0.1µF
D1 D8 D10 D13: "LED, Green, SMD", Color=Green, Manufacturer=Kingbright, Power_TotalModule=0.075, Supplier Part Number 1=46W4594, Value1=0.075W, Value2=2.1V
D2 D9: "LED, Red, SMD", Color=Red, Manufacturer=Kingbright, Power_TotalModule=0.075, Supplier Part Number 1=46W4604, Value1=0.075W, Value2=1.95V
D3 D4: "Diode, Schottky, 40V, 0.35A, SOD-523", Manufacturer="Diodes Inc.", Supplier Part Number 1=ZHCS350TACT-ND, Value1=0.35A, Value2=0.65V
D5: "Diode, Schottky, 30 V, 0.2 A, SOT-23", Manufacturer="Diodes Inc.", Supplier Part Number 1=BAT54C-FDICT-ND, Value1=0.2A, Value2=0.65V
D6 D7: "Diode, TVS, Bi, 7 V, SOT-23", Manufacturer=Bourns, Supplier Part Number 1=CDSOT23-SM712CT-ND, Value1=W
D11: "Diode, TVS, Uni, 5 V, 13.4 Vc, SMA", Manufacturer=STMicroelectronics, Supplier Part Number 1=497-2999-1-ND, Value1=W
F1 F2: "Fuse, 0.5 A, 125VAC/VDC, SMD", Irating_A=0.5, Manufacturer=Littelfuse, Supplier Part Number 1=F1163CT-ND
FID1 FID2 FID3: "Fiducial mark.  There is nothing to buy or mount.", Manufacturer=N/A
FL1: "Filter, BandPass, 2.45GHz, SMD", Manufacturer=MuRata
J1 J11: "Header, 2.54mm, 10x1, Gold, TH", Color=Black, Manufacturer="Wurth Elektronik", Supplier Part Number 1=732-2670-ND
J2: "SMA Jack, 50 Ohm, Gold, R/A, SMT", Manufacturer=Samtec, Supplier Part Number 1=SAM8857-ND, Voltage_V=335
J3 J6: "Header, 50mil, 5x2, Gold, TH", Manufacturer="Sullins Connector Solutions", Supplier Part Number 1=S9015E-05-ND
J4: "Connector, FPC 10 Pos. 9.1x2.0x5.6 mm", Manufacturer="Hirose Electric Co. Ltd."
J5: "Receptacle, D-Sub, 2.29mm, 27 Pos, Gold, R/A, TH", Color=Black, Current_A=3, Manufacturer="Wurth Elektronik", Supplier Part Number 1=16T0678, Voltage_V=60
L1 L6: "Ferrite Bead, 1500 ohm @ 100 MHz, 0.5 A, 0603", Manufacturer=MuRata, Supplier Part Number 1=490-5216-1-ND, Value1="0.5 ohm", Value2=0.5A
L2: "Inductor, Multilayer, Ferrite, 10 µH, 0.11 A, 0.52 ohm, SMD", Manufacturer="Taiyo Yuden", Supplier Part Number 1=587-2608-1-ND, Value1="0.52 ohm", Value2=0.11A, ValueDisplayed=10µH
L3 L4: "Inductor, Multilayer, Ferrite, 4.7 µH, 0.3 A, 0.143 ohm, SMD", Manufacturer=TDK, Supplier Part Number 1=445-6378-1-ND, Value1="0.143 ohm", Value2=0.3A, ValueDisplayed=4.7µH
L5: "Ferrite Bead, 1000 ohm @ 100 MHz, 0.25 A, 0402", Manufacturer=MuRata, Supplier Part Number 1=490-3999-1-ND, Value1="1.1 ohm", Value2=0.25A, ValueDisplayed="1000 ohm"
L7: "Inductor, Shielded Drum Core, Ferrite, 100 µH, 0.45 A, 0.36 ohm, SMD", Manufacturer="Wurth Elektronik", Supplier Part Number 1=732-1052-1-ND, Value1="0.36 ohm", Value2=0.45A, ValueDisplayed=100µH
Logo1: library part TI_Logo, "Texas Instrument Corporate Signature"
Logo2: library part Pb-Free
Logo3: library part FCC_disclaimer, "FCC_disclaimer"
R1 R2: "RES, 0, 5%, 0.063 W, 0402", Manufacturer=Vishay-Dale, Power_W=0.063, Supplier Part Number 1=541-0.0JCT-ND, TempCo="200 ppm/C", Tolerance_%=5, Value1=5%, Value2=0.063W, Value_Code=0000, ValueDisplayed=0
R4 R5 R33 R38 R39 R40: "RES, 470, 5%, 0.063 W, 0402", Manufacturer=Vishay-Dale, Power_W=0.063, Supplier Part Number 1=541-470JCT-ND, TempCo="200 ppm/C", Tolerance_%=5, Value1=5%, Value2=0.063W, Value_Code=470R, ValueDisplayed=470
R8: "RES, 47.5 k, 1%, 0.063 W, 0402", Manufacturer=Vishay-Dale, Power_W=0.063, Supplier Part Number 1=541-47.5KLCT-ND, TempCo="100 ppm/C", Tolerance_%=1, Value1=1%, Value2=0.063W, Value_Code=47k5, ValueDisplayed=47.5k
R9: "RES, 100 k, 5%, 0.063 W, 0402", Manufacturer=Vishay-Dale, Power_W=0.063, Supplier Part Number 1=541-100KJCT-ND, TempCo="200 ppm/C", Tolerance_%=5, Value1=5%, Value2=0.063W, Value_Code=100k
